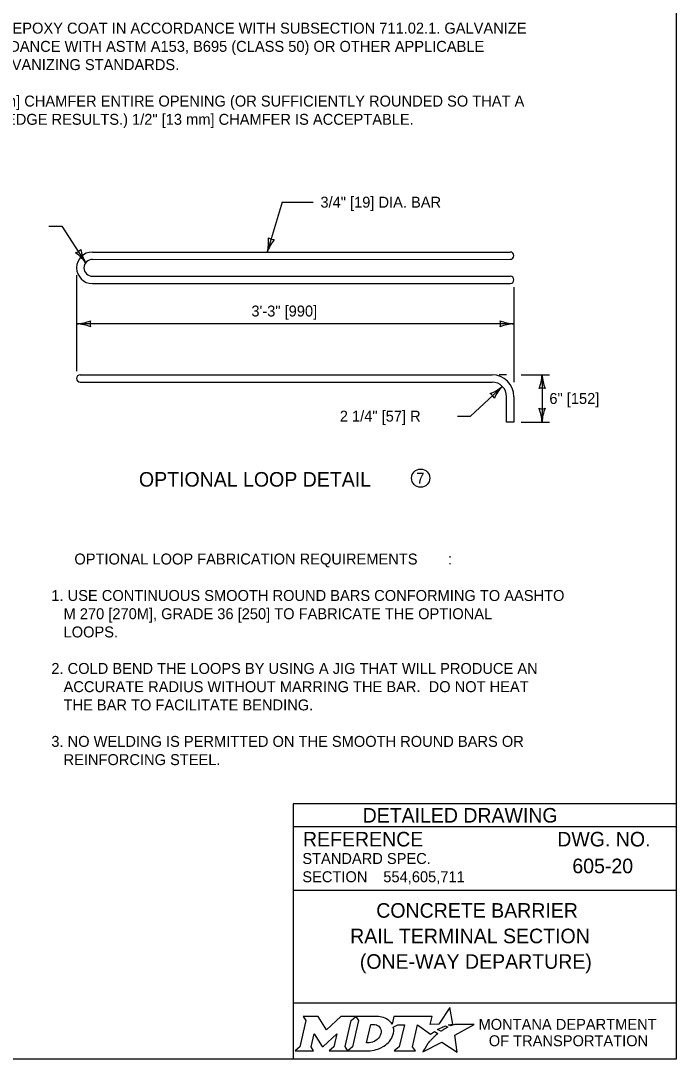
# Model space of a CAD drawing. Extents: x 49991.4 to 50021, y 49987.6 to 50011.4.
# Drawn here: x 50013.16 to 50016.75, y 49987.8 to 49993.49 of the extents above; entities that cross this region are included whole.
import ezdxf

# ---------------------------------------------------------------- set-up
doc = ezdxf.new("R2010")
doc.units = 0
for name, color, linetype in [('Default', 7, 'Continuous'), ('Level 1', 7, 'Continuous'), ('Level 2', 7, 'Continuous'), ('Level 3', 7, 'Continuous'), ('Level 5', 7, 'Continuous')]:
    doc.layers.add(name, color=color, linetype=linetype)

msp = doc.modelspace()

# ---------------------------------------------------------------- linework, layer by layer
at = {"layer": 'Default'}
for points in [[(50014.7056, 49988.0338), (50014.7197, 49988.0104), (50014.6862, 49987.8671), (50014.6605, 49987.8446), (50014.7621, 49987.8446), (50014.7486, 49987.8674), (50014.7648, 49987.9375), (50014.8085, 49987.8685), (50014.8138, 49987.8685), (50014.8889, 49987.938), (50014.8725, 49987.8669), (50014.8478, 49987.8449), (50014.9494, 49987.8449), (50014.9356, 49987.8682), (50014.9688, 49988.0106)], [(50014.9688, 49988.0106), (50014.9941, 49988.0338), (50014.9117, 49988.0338), (50014.8321, 49987.9608), (50014.7876, 49988.0335), (50014.7056, 49988.0338)], [(50015.1077, 49988.0338), (50014.9941, 49988.0338), (50015.0088, 49988.0109), (50014.9749, 49987.8671), (50014.9494, 49987.8449), (50015.06, 49987.8449)], [(50015.5126, 49987.9811), (50015.5023, 49987.9867), (50015.5139, 49987.9895), (50015.5255, 49987.9915), (50015.5081, 49988.0816), (50015.4486, 49987.9903), (50015.4013, 49987.9896), (50015.4116, 49988.0337), (50015.2024, 49988.0338), (50015.1923, 49987.9913), (50015.1865, 49987.9996)], [(50015.1317, 49987.9471), (50015.1305, 49987.939), (50015.1273, 49987.9297), (50015.1231, 49987.9215), (50015.1175, 49987.914), (50015.111, 49987.9071), (50015.1031, 49987.9008), (50015.0948, 49987.8961), (50015.0857, 49987.8922), (50015.0766, 49987.8899), (50015.0674, 49987.889), (50015.0515, 49987.889), (50015.0751, 49987.989), (50015.0911, 49987.989), (50015.0987, 49987.9884), (50015.1063, 49987.9865), (50015.1129, 49987.9835), (50015.119, 49987.9793), (50015.1238, 49987.9743), (50015.1275, 49987.9683), (50015.1302, 49987.9621), (50015.1318, 49987.9547), (50015.1318, 49987.9517), (50015.1317, 49987.9471)], [(50015.1991, 49987.9747), (50015.2237, 49987.9878), (50015.2606, 49987.9878), (50015.232, 49987.8673), (50015.2045, 49987.8446), (50015.3207, 49987.8446), (50015.3037, 49987.8675), (50015.3319, 49987.9877), (50015.4032, 49987.936), (50015.4243, 49987.9511), (50015.444, 49987.9402)], [(50015.3882, 49987.8843), (50015.3729, 49987.8599), (50015.3682, 49987.8524), (50015.3624, 49987.8438), (50015.3601, 49987.8395), (50015.4654, 49987.8926), (50015.5493, 49987.8375), (50015.5362, 49987.9302), (50015.6431, 49987.9886), (50015.5938, 49987.9894), (50015.5637, 49987.9898), (50015.5429, 49987.9901), (50015.5361, 49987.9886), (50015.5312, 49987.9874), (50015.5228, 49987.9851), (50015.5126, 49987.9811)], [(50015.4622, 49987.9535), (50015.4598, 49987.9518), (50015.4415, 49987.9614), (50015.4518, 49987.9671), (50015.4559, 49987.9693), (50015.4645, 49987.9733), (50015.4702, 49987.9759), (50015.4781, 49987.9789), (50015.4854, 49987.9816), (50015.4972, 49987.9742), (50015.4932, 49987.9721), (50015.4886, 49987.9696), (50015.4844, 49987.9674), (50015.4794, 49987.9645), (50015.4775, 49987.9634), (50015.4748, 49987.9618), (50015.4723, 49987.9604), (50015.47, 49987.9588), (50015.4674, 49987.957), (50015.4647, 49987.9552), (50015.4622, 49987.9535)], [(50015.1057, 49987.8522), (50015.1141, 49987.8548), (50015.1271, 49987.8602), (50015.1475, 49987.8712)], [(50015.4021, 49987.9004), (50015.4021, 49987.9004)]]:
    msp.add_lwpolyline(points, dxfattribs=at)
for centre, radius, start, end in [((50015.1308, 49987.9554), 0.0709, 339.5329, 15.8582), ((50015.0868, 49987.9727), 0.1183, 300.9103, 339.1383)]:
    msp.add_arc(centre, radius, start, end, dxfattribs=at)
for centre, major_axis, ratio, start_param, end_param in [((50015.1056, 49987.9864), (0.0834, -0.0037), 0.568097, 0.61298, 1.570796), ((50015.1612, 49987.9937), (0.0361, -0.0295), 0.469099, 1.225588, 1.570796), ((50015.4119, 49987.9106), (-0.0098, -0.0102), 0.016458, 3.141593, 6.279097), ((50015.4329, 49987.9305), (-0.0112, -0.0097), 0.021651, 3.157348, 6.283185), ((50015.3952, 49987.8923), (-0.00694, -0.00806), 0.008222, 0, 3.137361), ((50015.0603, 49987.9932), (0, 0.1484), 0.987302, 3.139398, 3.456847)]:
    msp.add_ellipse(centre, major_axis=major_axis, ratio=ratio, start_param=start_param, end_param=end_param, dxfattribs=at)
at = {"layer": 'Level 1'}
for p, q in [((50013.5497, 49992.2248), (50015.8404, 49992.2249)), ((50013.5497, 49992.1846), (50015.8404, 49992.1849)), ((50013.5497, 49992.0917), (50015.8404, 49992.0919)), ((50013.5497, 49992.0516), (50015.8404, 49992.0519)), ((50013.4822, 49991.5518), (50015.7402, 49991.5518)), ((50013.4822, 49991.5117), (50015.7402, 49991.5117)), ((50015.8202, 49991.2918), (50015.8202, 49991.4317)), ((50015.8604, 49991.4317), (50015.8604, 49991.2918)), ((50015.8604, 49991.2918), (50015.8202, 49991.2918))]:
    msp.add_line(p, q, dxfattribs=at)
msp.add_lwpolyline([(49999.3835, 49998.9992), (50016.7501, 49998.9992), (50016.7501, 49987.7988), (49999.3835, 49987.7988)], close=True, dxfattribs=at)
for centre, radius, start, end in [((50013.5497, 49992.1382), 0.0866, 90, 270), ((50015.8404, 49992.2049), 0.02, 270, 90), ((50013.5497, 49992.1382), 0.0465, 90, 270), ((50015.8404, 49992.0719), 0.02, 270, 90), ((50013.4831, 49991.5318), 0.0201, 92.8027, 267.1973), ((50015.7394, 49991.4308), 0.121, 0.4343, 89.6039), ((50015.7402, 49991.4317), 0.08, 360, 90)]:
    msp.add_arc(centre, radius, start, end, dxfattribs=at)
at = {"layer": 'Level 2'}
msp.add_ellipse((50015.3494, 49990.9851), major_axis=(0.05, 0), ratio=0.9994, dxfattribs=at)
at = {"layer": 'Level 3'}
for p, q in [((50014.5903, 49992.498), (50014.5084, 49992.2249)), ((50014.5903, 49992.498), (50014.7595, 49992.498)), ((50013.311, 49992.3673), (50013.3823, 49992.3673)), ((50013.3822, 49992.3673), (50013.5125, 49992.166)), ((50013.4631, 49992.0982), (50013.4631, 49991.5718)), ((50015.8604, 49992.0319), (50015.8604, 49991.5117)), ((50015.8604, 49991.8313), (50013.4631, 49991.8313)), ((50015.8204, 49991.5518), (50015.7802, 49991.5518)), ((50015.9004, 49991.5518), (50016.0547, 49991.5518)), ((50016.0147, 49991.5518), (50016.0147, 49991.2918)), ((50015.6216, 49991.325), (50015.797, 49991.4881)), ((50015.5503, 49991.325), (50015.6216, 49991.325)), ((50015.9004, 49991.2918), (50016.0547, 49991.2918))]:
    msp.add_line(p, q, dxfattribs=at)
for centre, radius, start, end in [((50014.2822, 49992.2808), 0.233, 346.123, 5.3729), ((50014.5453, 49992.3477), 0.0548, 235.4345, 271.1569), ((50014.7185, 49992.1523), 0.2223, 140.7517, 160.9352), ((50013.4428, 49992.2737), 0.0548, 285.0528, 320.7752), ((50013.3234, 49992.0299), 0.233, 35.7413, 54.9912), ((50013.7039, 49992.279), 0.2223, 190.37, 210.5535), ((50013.4516, 49992.064), 0.233, 272.8273, 292.0772), ((50013.5913, 49991.8313), 0.0548, 162.1388, 197.8612), ((50015.8695, 49992.0534), 0.2223, 247.456, 267.6395), ((50015.7322, 49991.8313), 0.0548, 342.1388, 17.8612), ((50013.4539, 49991.6092), 0.2223, 67.456, 87.6395), ((50015.8719, 49991.5986), 0.233, 92.8273, 112.0772), ((50015.7926, 49991.561), 0.2223, 337.456, 357.6395), ((50016.2474, 49991.5633), 0.233, 182.8273, 202.0772), ((50015.6525, 49991.657), 0.2223, 290.37, 310.5535), ((50015.7031, 49991.4008), 0.0548, 25.0528, 60.7752), ((50015.9639, 49991.3255), 0.233, 135.7413, 154.9912), ((50016.0147, 49991.4236), 0.0548, 72.1388, 107.8612), ((50016.0147, 49991.42), 0.0548, 252.1388, 287.8612), ((50015.782, 49991.2803), 0.233, 2.8273, 22.0772), ((50016.2368, 49991.2827), 0.2223, 157.456, 177.6395)]:
    msp.add_arc(centre, radius, start, end, dxfattribs=at)
at = {"layer": 'Level 5'}
for p, q in [((50016.7501, 49989.1988), (50014.6501, 49989.1988)), ((50014.6501, 49989.1988), (50014.6501, 49987.7988)), ((50016.7501, 49989.0738), (50014.6501, 49989.0738)), ((50016.3862, 49988.8587), (50016.3862, 49988.8587)), ((50015.1444, 49988.7993), (50015.1444, 49988.7993)), ((50016.7501, 49988.7238), (50014.6501, 49988.7238)), ((50015.7001, 49988.4747), (50015.7001, 49988.4747)), ((50016.7501, 49988.1057), (50014.6501, 49988.1057))]:
    msp.add_line(p, q, dxfattribs=at)

# ---------------------------------------------------------------- texts
at = {"layer": 'Default'}
for s, p in [('MONTANA DEPARTMENT', (50015.6663, 49987.96)), ('OF TRANSPORTATION', (50015.7225, 49987.87))]:
    msp.add_text(s, height=0.06, dxfattribs=at).set_placement(p)
at = {"layer": 'Level 2'}
for s, height, p in [('BENDING. EPOXY COAT IN ACCORDANCE WITH SUBSECTION 711.02.1. GALVANIZE', 0.06, (50012.7015, 49993.4224)), ('IN ACCORDANCE WITH ASTM A153, B695 (CLASS 50) OR OTHER APPLICABLE', 0.06, (50012.7015, 49993.3224)), ('ASTM GALVANIZING STANDARDS. ', 0.06, (50012.7015, 49993.2224)), ('3/4" [19 mm] CHAMFER ENTIRE OPENING (OR SUFFICIENTLY ROUNDED SO THAT A', 0.06, (50012.7015, 49993.0224)), ('SMOOTH EDGE RESULTS.) 1/2" [13 mm] CHAMFER IS ACCEPTABLE.  ', 0.06, (50012.7015, 49992.9224)), ('3\'-3" [990]', 0.06, (50014.4211, 49991.8713)), ('6" [152]', 0.06, (50016.0547, 49991.3919)), ('2 1/4" [57] R', 0.06, (50014.9058, 49991.295)), ('OPTIONAL LOOP DETAIL', 0.08, (50013.8047, 49990.9384)), ('7', 0.06, (50015.3256, 49990.9551)), ('OPTIONAL LOOP FABRICATION REQUIREMENTS', 0.06, (50013.4507, 49990.5115)), (':', 0.06, (50015.4991, 49990.5115)), ('1. USE CONTINUOUS SMOOTH ROUND BARS CONFORMING TO AASHTO ', 0.06, (50013.3245, 49990.3115)), ('   M 270 [270M], GRADE 36 [250] TO FABRICATE THE OPTIONAL ', 0.06, (50013.3245, 49990.2115)), ('   LOOPS.   ', 0.06, (50013.3245, 49990.1115)), ('2. COLD BEND THE LOOPS BY USING A JIG THAT WILL PRODUCE AN ', 0.06, (50013.3245, 49989.9115)), ('   ACCURATE RADIUS WITHOUT MARRING THE BAR.  DO NOT HEAT ', 0.06, (50013.3245, 49989.8115)), ('   THE BAR TO FACILITATE BENDING.', 0.06, (50013.3245, 49989.7115)), ('3. NO WELDING IS PERMITTED ON THE SMOOTH ROUND BARS OR ', 0.06, (50013.3245, 49989.5115)), ('   REINFORCING STEEL.', 0.06, (50013.3245, 49989.4115)), ('605-20', 0.08, (50016.1806, 49988.8187)), ('554,605,711', 0.06, (50015.1444, 49988.7693)), ('CONCRETE BARRIER', 0.08, (50015.1056, 49988.5747)), ('RAIL TERMINAL SECTION', 0.08, (50014.9624, 49988.4347)), ('(ONE-WAY DEPARTURE)', 0.08, (50015.0156, 49988.2947))]:
    msp.add_text(s, height=height, dxfattribs=at).set_placement(p)
msp.add_text('3/4" [19] DIA. BAR', height=0.06, rotation=360, dxfattribs=at).set_placement((50014.7995, 49992.468))
at = {"layer": 'Level 5'}
for s, height, p in [('DETAILED DRAWING', 0.0799, (50015.0311, 49989.0963)), ('REFERENCE', 0.08, (50014.7037, 49988.9654)), ('DWG. NO.', 0.08, (50016.0979, 49988.9654)), ('STANDARD SPEC.', 0.06, (50014.7004, 49988.8694)), ('SECTION', 0.06, (50014.7004, 49988.7694))]:
    msp.add_text(s, height=height, dxfattribs=at).set_placement(p)

doc.saveas('drawing.dxf')
